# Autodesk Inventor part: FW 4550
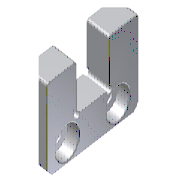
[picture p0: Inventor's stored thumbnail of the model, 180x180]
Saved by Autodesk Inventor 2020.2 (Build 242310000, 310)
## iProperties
Manager: www.cadconsulting.pl
Company: Fabian Stasiak CAD Consulting
Created: 2014-02
Part Number: FW 4550
Material: 1.7131
Description: Straight interlocks
Document SubType Name: Modeling
Designer: F.Stasiak
Standard Revision: 1
Manufacturer: DME
Language: pl-PL
Size Designation: 50
Categories: <MemberInstance><Categories><Category DisplayName="Forma wtryskowa" InternalName="349578f2-f4d4-4954-8c09-8e99297a61c0" Mnemonic="MOLD"><Category DisplayName="E
Density: 7.85 g/cm^3
Appearance: Domyślna
Catalog Web Link: www.expertbooks.pl
IsCustomPart: 1
Author: F.Stasiak
Subject: Zbiór ćwiczeń. Autodesk Inventor 2020. Kurs Professional
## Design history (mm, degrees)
sketch "Sketch1"
  geometry: L1 (-25, 0)-(-10, 0); L2 (-10, 0)-(-10, -18); L3 (-9, -19)-(9, -19); L4 (10, -18)-(10, 0); L5 (10, 0)-(25, 0); L6 (25, 0)-(25, -36); L7 (25, -36)-(-25, -36); L8 (-25, -36)-(-25, 0); L9 (0, 5.4)-(0, -32.4) reference; L10 (-28, 0)-(28, 0) reference; A1 r 1 centre (-10, -19) between (-10, -18) and (-9, -19); A2 r 1 centre (10, -19) between (9, -19) and (10, -18); 1 further point
  constraints: 16 end point, 5 parallel, 4 point on circle, 4 point on line, 3 collinear, 2 centre point, 1 horizontal, 1 perpendicular, 2 other
  dimensions: "d0" = 50 distance between parallel lines of L6 L8 (= b); "d1" = 36 distance between parallel lines of L7 L1 (= s2); "d2" = 17 distance between parallel lines of L7 L3 (= s1); "d3" = 20 distance between parallel lines of L2 L4 (= b1); "d28" = 2 diameter of A1 (= R3); "d29" = 2 diameter of A2 (= R3)
extrude "Extrusion1" new body sketch "Sketch1" distance "d4" = 12.5 (= h_); taper "d5" = 0 deg
sketch "Sketch2"
  geometry: L1 (-7.2, 0)-(43.2, 0) reference; L2 (36, 25)-(36, -25) reference; 3 further points
  constraints: 1 symmetric about line, 1 vertical alignment
  dimensions: "d6" = 32 distance of point (27.5, -16) point (27.5, 16) (= b2); "d7" = 8.5 distance from line of L2 point (27.5, 16) (= a)
hole "Hole1" sketch "Sketch2" diameter "d8" = 6.6 (= D2); stored, may be unused: countersink angle "d12" = 90 deg, drill point angle "d14" = 0 deg; dims "d9" = 6, "d10" = 11 (= D1), "d11" = 6 (= M), "d13" = 12.5 (= h_)
hole "Hole2" sketch "Sketch2" diameter "d15" = 6.6 (= D2); stored, may be unused: countersink angle "d19" = 90 deg, drill point angle "d21" = 0 deg; dims "d16" = 6, "d17" = 11 (= D1), "d18" = 6 (= M), "d20" = 12.5 (= h_)
chamfer "Chamfer1" distance "d22" = 3 (= f1); stored, may be unused: second distance "d23" = 2, angle "d24" = 45 deg
chamfer "Chamfer2" distance "d25" = 6.5 (= f_); stored, may be unused: second distance "d26" = 2, angle "d27" = 45 deg
fillet "Fillet1" dims "d30" = 1 (= R1)
fillet "Fillet2" dims "d31" = 0.5 (= C1)
sketch "Sketch3"
  geometry: L1 (-1, 25)-(-33, 25) reference; L2 (-36, 19)-(-36, -19) reference; L3 (-33, -25)-(-1, -25) reference; L4 (0, 11)-(0, 19) reference; L5 (-36, 25)-(0, 25); L6 (0, 25)-(0, -25); L7 (0, -25)-(-36, -25); L8 (-36, -25)-(-36, 25); 1 further point
  constraints: 8 end point, 4 collinear, 2 parallel, 1 horizontal, 1 perpendicular
extrude_surface "ExtrusionSrf1" sketch "Sketch3" dims "d32" = 25 (= 2 x h_), "d33" = 0
fillet "Fillet3" dims "d34" = 2 (= R3)
feature "Stitch Surface1" dims "d41" = 0.254 (derived)
body "Solid1"
body "Srf1"
body "Srf2"
body "Srf3"
body "Srf4"
patch "Boundary Patch1" dims "d35" = 0, "d36" = 0, "d37" = 0
patch "Boundary Patch2" dims "d38" = 0, "d39" = 0, "d40" = 0
other parameters: "b" = 50 [user parameter; used in 1 equation term], "a" = 8.5 [user parameter; used in 1 equation term], "b1" = 20 [user parameter; used in 1 equation term], "b2" = 32 [user parameter; used in 1 equation term], "f_" = 6.5 [user parameter; used in 1 equation term], "f1" = 3 [user parameter; used in 1 equation term], "h_" = 12.5 [user parameter; used in 4 equation terms], "s1" = 17 [user parameter; used in 1 equation term], "s2" = 36 [user parameter; used in 1 equation term], "D1" = 11 [user parameter; used in 2 equation terms], "D2" = 6.6 [user parameter; used in 2 equation terms], "M" = 6 [user parameter; used in 2 equation terms], "C1" = 0.5 [user parameter; used in 1 equation term], "R1" = 1 [user parameter; used in 1 equation term], "R3" = 2 [user parameter; used in 3 equation terms]
